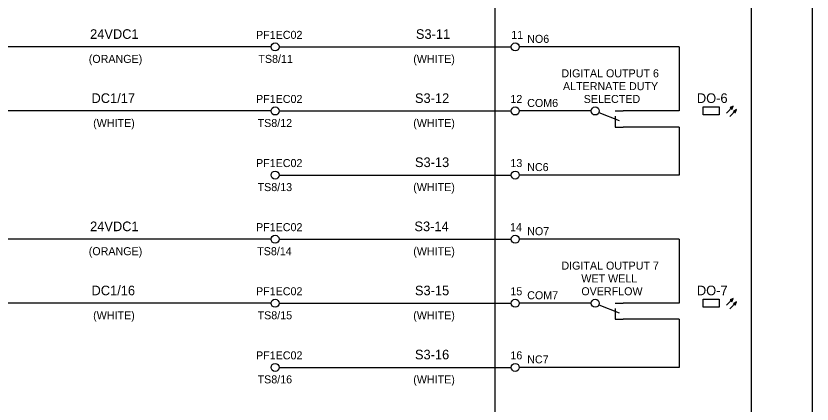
# Model space of a CAD drawing. Extents: x 0 to 841, y 0 to 594.
# Drawn here: x 580.3 to 829, y 168.6 to 289.7 of the extents above; entities that cross this region are included whole.
import ezdxf

# ---------------------------------------------------------------- set-up
doc = ezdxf.new("R2010")
doc.units = 0
for name, color, linetype in [('A1BORDER', 7, 'Continuous'), ('Level 1', 7, 'Continuous'), ('Level 10', 7, 'Continuous')]:
    doc.layers.add(name, color=color, linetype=linetype)

msp = doc.modelspace()

# ---------------------------------------------------------------- linework, layer by layer
at = {"layer": 'A1BORDER'}
msp.add_line((829, 581), (829, 15), dxfattribs=at)
at = {"layer": 'Level 1'}
for p, q in [((660, 280), (360, 280)), ((662.5, 280), (735, 280)), ((787.5, 280), (737.5, 280)), ((787.5, 280), (787.5, 260)), ((660, 260), (360, 260)), ((662.5, 260), (735, 260)), ((760, 260), (737.5, 260)), ((787.5, 260), (770, 260)), ((787.5, 255), (770, 255)), ((787.5, 255), (787.5, 240)), ((662.5, 240), (735, 240)), ((787.5, 240), (737.5, 240)), ((660, 220), (360, 220)), ((662.5, 220), (735, 220)), ((787.5, 220), (737.5, 220)), ((787.5, 220), (787.5, 200)), ((660, 200), (360, 200)), ((662.5, 200), (735, 200)), ((760, 200), (737.5, 200)), ((787.5, 200), (770, 200)), ((787.5, 195), (770, 195)), ((787.5, 195), (787.5, 180)), ((662.5, 180), (735, 180)), ((787.5, 180), (737.5, 180))]:
    msp.add_line(p, q, dxfattribs=at)
for points in [[(730, 540), (810, 540), (810, 80), (730, 80)], [(795, 261.25), (800, 261.25), (800, 258.75), (795, 258.75)], [(795, 201.25), (800, 201.25), (800, 198.75), (795, 198.75)]]:
    msp.add_lwpolyline(points, close=True, dxfattribs=at)
for centre in [(661.25, 280), (736.25, 280), (661.25, 260), (736.25, 260), (661.25, 240), (736.25, 240), (661.25, 220), (736.25, 220), (661.25, 200), (736.25, 200), (661.25, 180), (736.25, 180)]:
    msp.add_circle(centre, 1.25, dxfattribs=at)
at = {"layer": 'Level 10'}
for p, q in [((802.23, 259.36), (804.36, 261.48)), ((803.79, 261.23), (804.24, 261.23)), ((804.12, 261.38), (804.31, 261.38)), ((762.41, 259.54), (768.75, 257)), ((767.5, 260), (770, 260)), ((803.29, 258.3), (805.41, 260.42)), ((803.46, 261.07), (804.17, 261.07)), ((803.5, 260.93), (804.11, 260.93)), ((803.64, 260.77), (804.03, 260.77)), ((803.8, 260.62), (803.97, 260.62)), ((804.52, 260.01), (805.23, 260.01)), ((804.56, 259.87), (805.16, 259.87)), ((804.71, 259.72), (805.1, 259.72)), ((804.85, 260.17), (805.3, 260.17)), ((804.86, 259.56), (805.03, 259.56)), ((805.18, 260.31), (805.37, 260.31)), ((767.5, 258.37), (767.5, 255)), ((767.5, 255), (770, 255)), ((802.23, 199.36), (804.36, 201.48)), ((762.41, 199.54), (768.75, 197)), ((767.5, 200), (770, 200)), ((803.29, 198.3), (805.41, 200.42)), ((803.46, 201.08), (804.17, 201.08)), ((803.5, 200.93), (804.11, 200.93)), ((803.64, 200.78), (804.03, 200.78)), ((803.79, 201.22), (804.24, 201.22)), ((803.8, 200.62), (803.97, 200.62)), ((804.12, 201.38), (804.31, 201.38)), ((804.52, 200.02), (805.23, 200.02)), ((804.56, 199.87), (805.16, 199.87)), ((804.71, 199.72), (805.1, 199.72)), ((804.85, 200.16), (805.3, 200.16)), ((804.86, 199.56), (805.03, 199.56)), ((805.18, 200.31), (805.37, 200.31)), ((767.5, 198.37), (767.5, 195)), ((767.5, 195), (770, 195))]:
    msp.add_line(p, q, dxfattribs=at)
for points in [[(804.36, 261.48), (803.38, 261.04), (803.91, 260.5)], [(805.41, 260.42), (804.44, 259.98), (804.98, 259.44)], [(804.36, 201.48), (803.38, 201.04), (803.91, 200.5)], [(805.41, 200.42), (804.44, 199.98), (804.98, 199.44)]]:
    msp.add_lwpolyline(points, close=True, dxfattribs=at)
for centre in [(761.25, 260), (761.25, 200)]:
    msp.add_circle(centre, 1.25, dxfattribs=at)

# ---------------------------------------------------------------- texts
at = {"layer": 'Level 1'}
for s, height, p in [('24VDC1', 3, (603.43, 282.5)), ('PF1EC02', 2.5, (655.28, 282.5)), ('S3-11', 3, (705.22, 282.5)), ('11', 2.5, (735.01, 282.5)), ('NO6', 2.5, (740, 281.25)), ('(ORANGE)', 2.5, (603.02, 275)), ('TS8/11', 2.5, (656.02, 275)), ('(WHITE)', 2.5, (704.4, 275)), ('DIGITAL OUTPUT 6', 2.5, (750.68, 270.5)), ('ALTERNATE DUTY', 2.5, (751.18, 266.5)), ('DC1/17', 3, (603.88, 262.5)), ('PF1EC02', 2.5, (655.28, 262.5)), ('S3-12', 3, (704.93, 262.5)), ('12', 2.5, (734.75, 262.5)), ('COM6', 2.5, (740, 261.25)), ('SELECTED', 2.5, (757.65, 262.5)), ('DO-6', 3, (793.02, 262.5)), ('(WHITE)', 2.5, (604.39, 255)), ('TS8/12', 2.5, (655.77, 255)), ('(WHITE)', 2.5, (704.4, 255)), ('PF1EC02', 2.5, (655.28, 242.5)), ('S3-13', 3, (704.93, 242.5)), ('13', 2.5, (734.75, 242.5)), ('NC6', 2.5, (740, 241.25)), ('TS8/13', 2.5, (655.77, 235)), ('(WHITE)', 2.5, (704.4, 235)), ('24VDC1', 3, (603.43, 222.5)), ('PF1EC02', 2.5, (655.28, 222.5)), ('S3-14', 3, (704.77, 222.5)), ('14', 2.5, (734.63, 222.5)), ('NO7', 2.5, (740, 221.25)), ('(ORANGE)', 2.5, (603.02, 215)), ('TS8/14', 2.5, (655.65, 215)), ('(WHITE)', 2.5, (704.4, 215)), ('DIGITAL OUTPUT 7', 2.5, (750.68, 210.5)), ('WET WELL', 2.5, (756.91, 206.5)), ('DC1/16', 3, (603.88, 202.5)), ('PF1EC02', 2.5, (655.28, 202.5)), ('S3-15', 3, (704.93, 202.5)), ('15', 2.5, (734.75, 202.5)), ('OVERFLOW', 2.5, (756.91, 202.5)), ('DO-7', 3, (793.02, 202.5)), ('COM7', 2.5, (740, 201.25)), ('(WHITE)', 2.5, (604.39, 195)), ('TS8/15', 2.5, (655.77, 195)), ('(WHITE)', 2.5, (704.4, 195)), ('PF1EC02', 2.5, (655.28, 182.5)), ('S3-16', 3, (704.93, 182.5)), ('16', 2.5, (734.75, 182.5)), ('NC7', 2.5, (740, 181.25)), ('TS8/16', 2.5, (655.77, 175)), ('(WHITE)', 2.5, (704.4, 175))]:
    msp.add_text(s, height=height, dxfattribs=at).set_placement(p)

doc.saveas('drawing.dxf')
